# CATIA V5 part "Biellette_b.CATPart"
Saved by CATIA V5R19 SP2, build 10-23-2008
Part number: Biellette_b
Bounding box of the stored display mesh (mm): x 50 to 60, y -304 to -284, z -150.824 to -38
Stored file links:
  C:\Users\Pauline\Desktop\CFAO_Catia\Compte_rendu\pmayet_assemblage_animation4\Biellette_b.CATPart
  C:\Users\Pauline\Desktop\CFAO_Catia\Compte_rendu\pmayet_assemblage_animation4\pmayet_assemblage_animation.CATProduct
  C:\Users\Pauline\Desktop\CFAO_Catia\Compte_rendu\pmayet_assemblage_animation4\Squelette_biellette_b.CATPart
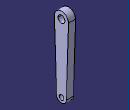
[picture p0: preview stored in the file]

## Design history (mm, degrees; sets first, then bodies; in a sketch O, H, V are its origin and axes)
Parameters
  Rayon_trou = 5 mm
  Rayon_trou_biellette = 3.5 mm
  Eapisseur_biellette_b = 5 mm
Set1
  Plane1: linked copy from another document
  Point1: linked copy from another document
  Plane2: linked copy from another document
  Point2: linked copy from another document
  Plane3: linked copy from another document
  Point3: linked copy from another document
Body1 (main body)
  Sketch1 on Plane1, origin (55, 0, 0), H (0, -1, 0), V (0, 0, 1)
    arc A1 centre (294, -144) radius 7 from (287, -144) to (301, -144) ccw
    point P1 (294, -144)
    point P2 (287, -144)
    point P3 (301, -144)
    reference projected point E1 (294, -144) from Point1
    reference intersected line E2 through (0, -144) direction (-1, 0) from Plane2
    reference intersected line E3 through (0, -144) direction (-1, 0) from Plane2
    arc A2 centre (294, -48) radius 10 from (304, -48) to (284, -48) ccw
    point P4 (294, -48)
    point P5 (304, -48)
    point P6 (284, -48)
    reference intersected line E4 through (0, -48) direction (-1, 0) from Plane3
    reference intersected line E5 through (0, -48) direction (-1, 0) from Plane3
    line L1 (284, -48) -> (287, -144)
    point P7 (284, -48)
    point P8 (287, -144)
    line L2 (304, -48) -> (301, -144)
    point P9 (304, -48)
    point P10 (301, -144)
    reference projected point E6 (294, -48) from Point3
    radius A1 = 7 {= Rayon_trou_biellette *2}
    distance E2 P2 = 0
    distance E3 P3 = 0
    radius A2 = 10 {= Rayon_trou *2}
    distance E4 P5 = 0
    distance E5 P6 = 0
    distance P8 P2 = 0
    distance P7 P6 = 0
    distance P9 P5 = 0
    distance P10 P3 = 0
    coincidence: P1 E1, P4 E6
  Pad1: profile Sketch1, direction (-1, 0, 0), length 5 {= Eapisseur_biellette_b}, mirrored extent
  Sketch2 on Plane1, origin (55, 0, 0), H (0, -1, 0), V (0, 0, 1)
    circle A1 centre (294, -48) radius 5
    point P1 (294, -48)
    reference projected point E1 (294, -48) from Point3
    distance P1 A1 = 5 {= Rayon_trou}
    coincidence: E1 P1
  Pocket1: profile Sketch2, direction (1, 0, 0), length 5 {= Eapisseur_biellette_b}, mirrored extent
  Sketch3 on Plane1, origin (55, 0, 0), H (0, -1, 0), V (0, 0, 1)
    circle A1 centre (294, -144) radius 3.5
    point P1 (294, -144)
    reference projected point E1 (294, -144) from Point1
    distance P1 A1 = 3.5 {= Rayon_trou_biellette}
    coincidence: P1 E1
  Pocket2: profile Sketch3, direction (1, 0, 0), length 5 {= Eapisseur_biellette_b}, mirrored extent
